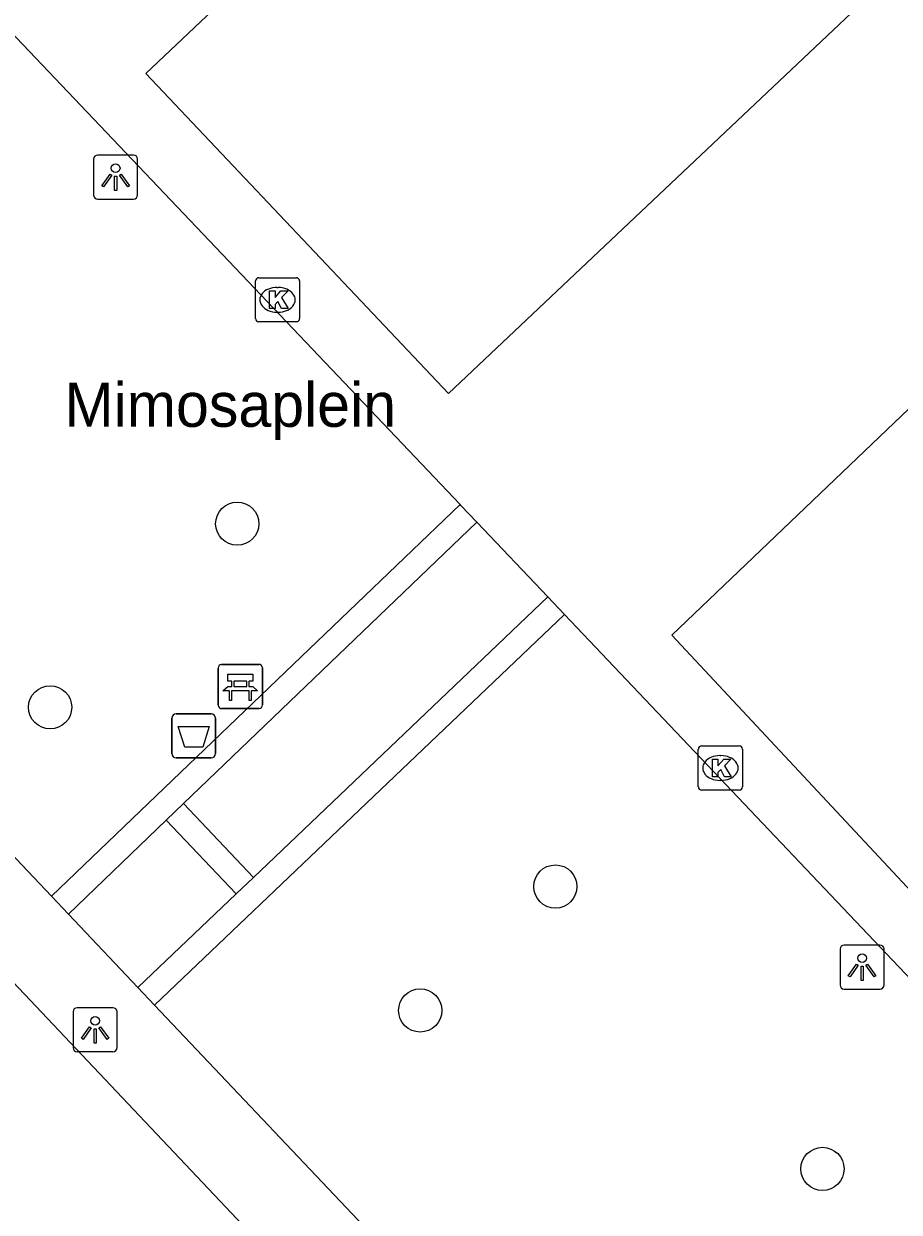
# Model space of a CAD drawing. Extents: x 162347 to 162868, y 381221 to 381813.
# Drawn here: x 162638.63 to 162658.45, y 381348.99 to 381375.9 of the extents above; entities that cross this region are included whole.
import ezdxf

# ---------------------------------------------------------------- set-up
doc = ezdxf.new("R2010")
doc.units = 0
for name, color, linetype in [('IMGEO_Afvalbak', 7, 'Continuous'), ('IMGEO_Bank', 7, 'Continuous'), ('IMGEO_Boom', 7, 'Continuous'), ('IMGEO_Kolk', 7, 'Continuous'), ('IMGEO_Lichtpunt', 7, 'Continuous'), ('IMGEO_Openbare_ruimte_label', 7, 'Continuous'), ('IMGEO_Rijbaan_lokaal_gesloten', 7, 'Continuous'), ('IMGEO_Rijbaan_lokaal_open', 7, 'Continuous'), ('IMGEO_Voetpad_open', 7, 'Continuous')]:
    doc.layers.add(name, color=color, linetype=linetype)

msp = doc.modelspace()

# ---------------------------------------------------------------- linework, layer by layer
at = {"layer": 'IMGEO_Afvalbak'}
for p, q in [((162641.982, 381359.38), (162641.982, 381360.18)), ((162641.982, 381360.18), (162641.982, 381359.38)), ((162642.082, 381360.28), (162642.872, 381360.28)), ((162642.872, 381360.28), (162642.082, 381360.28)), ((162642.972, 381360.18), (162642.972, 381359.38)), ((162642.972, 381359.38), (162642.972, 381360.18)), ((162642.872, 381359.28), (162642.082, 381359.28)), ((162642.082, 381359.28), (162642.872, 381359.28))]:
    msp.add_line(p, q, dxfattribs=at)
msp.add_lwpolyline([(162642.125, 381359.994), (162642.829, 381359.994), (162642.68, 381359.524), (162642.274, 381359.524), (162642.125, 381359.994)], dxfattribs=at)
for centre, start, end in [((162642.082, 381360.18), 90, 180), ((162642.082, 381360.18), 90, 180), ((162642.872, 381360.18), 0, 90), ((162642.872, 381360.18), 360, 90), ((162642.082, 381359.38), 180, 270), ((162642.082, 381359.38), 180, 270), ((162642.872, 381359.38), 270, 0), ((162642.872, 381359.38), 270, 0)]:
    msp.add_arc(centre, 0.1, start, end, dxfattribs=at)
at = {"layer": 'IMGEO_Bank'}
for p, q in [((162643.107, 381361.399), (162643.948, 381361.399)), ((162643.948, 381361.399), (162643.107, 381361.399)), ((162643.032, 381360.474), (162643.032, 381361.315)), ((162643.032, 381361.315), (162643.032, 381360.474)), ((162644.032, 381361.324), (162644.032, 381360.483)), ((162644.032, 381360.483), (162644.032, 381361.324)), ((162643.341, 381360.905), (162643.341, 381361.011)), ((162643.385, 381361.011), (162643.385, 381360.905)), ((162643.673, 381361.017), (162643.391, 381361.017)), ((162643.391, 381360.899), (162643.673, 381360.899)), ((162643.679, 381360.905), (162643.679, 381361.011)), ((162643.723, 381361.011), (162643.723, 381360.905)), ((162643.729, 381360.797), (162643.336, 381360.797)), ((162643.957, 381360.399), (162643.116, 381360.399)), ((162643.116, 381360.399), (162643.957, 381360.399))]:
    msp.add_line(p, q, dxfattribs=at)
for points in [[(162643.335, 381361.017), (162643.249, 381361.017), (162643.249, 381361.178), (162643.812, 381361.178), (162643.812, 381361.017), (162643.729, 381361.017)], [(162643.279, 381360.797), (162643.137, 381360.797), (162643.249, 381360.899), (162643.335, 381360.899)], [(162643.729, 381360.899), (162643.812, 381360.899), (162643.924, 381360.797), (162643.785, 381360.797)], [(162643.329, 381360.79), (162643.329, 381360.583), (162643.286, 381360.583), (162643.286, 381360.79)], [(162643.779, 381360.79), (162643.779, 381360.583), (162643.735, 381360.583), (162643.735, 381360.79)]]:
    msp.add_lwpolyline(points, dxfattribs=at)
for centre, radius, start, end in [((162643.11, 381361.321), 0.0779, 92.4484, 184.2845), ((162643.11, 381361.321), 0.0779, 92.4484, 184.2845), ((162643.954, 381361.321), 0.0779, 2.4484, 94.2845), ((162643.954, 381361.321), 0.0779, 2.4484, 94.2845), ((162643.334, 381361.01), 0.00671, 2.8957, 87.1043), ((162643.334, 381360.906), 0.00671, 272.8957, 357.1043), ((162643.391, 381361.01), 0.00671, 92.8957, 177.1043), ((162643.391, 381360.906), 0.00671, 182.8957, 267.1043), ((162643.673, 381361.01), 0.00671, 2.8957, 87.1043), ((162643.673, 381360.906), 0.00671, 272.8957, 357.1043), ((162643.73, 381361.01), 0.00671, 92.8957, 177.1043), ((162643.73, 381360.906), 0.00671, 182.8957, 267.1043), ((162643.279, 381360.79), 0.00671, 2.8957, 87.1043), ((162643.336, 381360.79), 0.00671, 92.8957, 177.1043), ((162643.728, 381360.79), 0.00671, 2.8957, 87.1043), ((162643.785, 381360.79), 0.00671, 92.8957, 177.1043), ((162643.11, 381360.477), 0.0779, 182.4484, 274.2845), ((162643.11, 381360.477), 0.0779, 182.4484, 274.2845), ((162643.954, 381360.477), 0.0779, 272.4484, 4.2845), ((162643.954, 381360.477), 0.0779, 272.4484, 4.2845)]:
    msp.add_arc(centre, radius, start, end, dxfattribs=at)
at = {"layer": 'IMGEO_Boom'}
for centre in [(162643.463, 381364.584), (162639.227, 381360.428), (162650.665, 381356.369), (162647.605, 381353.563), (162656.712, 381349.975)]:
    msp.add_circle(centre, 0.489, dxfattribs=at)
at = {"layer": 'IMGEO_Kolk'}
for p, q in [((162643.874, 381369.228), (162643.874, 381370.08)), ((162643.949, 381370.154), (162644.801, 381370.154)), ((162644.875, 381370.08), (162644.875, 381369.228)), ((162644.362, 381369.934), (162644.387, 381369.934)), ((162644.385, 381369.374), (162644.36, 381369.374)), ((162644.801, 381369.154), (162643.949, 381369.154)), ((162653.976, 381359.553), (162654.828, 381359.553)), ((162653.901, 381358.627), (162653.901, 381359.479)), ((162654.389, 381359.333), (162654.414, 381359.333)), ((162654.902, 381359.479), (162654.902, 381358.627)), ((162654.412, 381358.773), (162654.387, 381358.773)), ((162654.828, 381358.553), (162653.976, 381358.553))]:
    msp.add_line(p, q, dxfattribs=at)
for points in [[(162643.874, 381369.228), (162643.874, 381370.08)], [(162643.949, 381370.154), (162644.801, 381370.154)], [(162644.875, 381370.08), (162644.875, 381369.228)], [(162644.195, 381369.854), (162644.318, 381369.854), (162644.318, 381369.703), (162644.448, 381369.854), (162644.612, 381369.854), (162644.466, 381369.703), (162644.619, 381369.454), (162644.467, 381369.454), (162644.382, 381369.618), (162644.318, 381369.551), (162644.318, 381369.454), (162644.195, 381369.454), (162644.195, 381369.854)], [(162644.801, 381369.154), (162643.949, 381369.154)], [(162653.976, 381359.553), (162654.828, 381359.553)], [(162653.901, 381358.627), (162653.901, 381359.479)], [(162654.222, 381359.253), (162654.345, 381359.253), (162654.345, 381359.102), (162654.475, 381359.253), (162654.639, 381359.253), (162654.493, 381359.102), (162654.646, 381358.853), (162654.494, 381358.853), (162654.409, 381359.017), (162654.345, 381358.95), (162654.345, 381358.853), (162654.222, 381358.853), (162654.222, 381359.253)], [(162654.902, 381359.479), (162654.902, 381358.627)], [(162654.828, 381358.553), (162653.976, 381358.553)]]:
    msp.add_lwpolyline(points, dxfattribs=at)
for centre, start, end in [((162643.951, 381370.078), 91.552, 178.448), ((162643.951, 381370.078), 91.552, 178.448), ((162644.799, 381370.078), 1.552, 88.448), ((162644.799, 381370.078), 1.552, 88.448), ((162643.951, 381369.23), 181.552, 268.448), ((162643.951, 381369.23), 181.552, 268.448), ((162644.799, 381369.23), 271.552, 358.448), ((162644.799, 381369.23), 271.552, 358.448), ((162653.978, 381359.477), 91.552, 178.448), ((162653.978, 381359.477), 91.552, 178.448), ((162654.826, 381359.477), 1.552, 88.448), ((162654.826, 381359.477), 1.552, 88.448), ((162653.978, 381358.629), 181.552, 268.448), ((162653.978, 381358.629), 181.552, 268.448), ((162654.826, 381358.629), 271.552, 358.448), ((162654.826, 381358.629), 271.552, 358.448)]:
    msp.add_arc(centre, 0.0765, start, end, dxfattribs=at)
for centre, major_axis, ratio, start_param, end_param in [((162644.361, 381369.654), (-0.387, 0.002), 0.722429, 4.712389, 7.853982), ((162644.386, 381369.654), (-0.39, 0.002), 0.717154, 1.570796, 4.712389), ((162654.388, 381359.053), (-0.387, 0.002), 0.722429, 4.712389, 7.853982), ((162654.413, 381359.053), (-0.39, 0.002), 0.717154, 1.570796, 4.712389)]:
    msp.add_ellipse(centre, major_axis=major_axis, ratio=ratio, start_param=start_param, end_param=end_param, dxfattribs=at)
at = {"layer": 'IMGEO_Lichtpunt'}
for p, q in [((162640.21, 381372.837), (162640.21, 381372.03)), ((162640.21, 381372.837), (162640.21, 381372.03)), ((162641.112, 381372.932), (162640.304, 381372.932)), ((162641.112, 381372.932), (162640.304, 381372.932)), ((162641.206, 381372.03), (162641.206, 381372.837)), ((162641.206, 381372.03), (162641.206, 381372.837)), ((162640.304, 381371.936), (162641.112, 381371.936)), ((162640.304, 381371.936), (162641.112, 381371.936)), ((162657.11, 381354.949), (162657.11, 381354.142)), ((162657.11, 381354.949), (162657.11, 381354.142)), ((162658.012, 381355.044), (162657.204, 381355.044)), ((162658.012, 381355.044), (162657.204, 381355.044)), ((162658.106, 381354.142), (162658.106, 381354.949)), ((162658.106, 381354.142), (162658.106, 381354.949)), ((162657.204, 381354.048), (162658.012, 381354.048)), ((162657.204, 381354.048), (162658.012, 381354.048)), ((162640.648, 381353.626), (162639.84, 381353.626)), ((162640.648, 381353.626), (162639.84, 381353.626)), ((162639.746, 381353.531), (162639.746, 381352.724)), ((162639.746, 381353.531), (162639.746, 381352.724)), ((162640.742, 381352.724), (162640.742, 381353.531)), ((162640.742, 381352.724), (162640.742, 381353.531)), ((162639.84, 381352.63), (162640.648, 381352.63)), ((162639.84, 381352.63), (162640.648, 381352.63))]:
    msp.add_line(p, q, dxfattribs=at)
for points in [[(162640.584, 381372.501), (162640.623, 381372.473), (162640.435, 381372.211), (162640.397, 381372.238), (162640.584, 381372.501)], [(162640.686, 381372.453), (162640.733, 381372.453), (162640.733, 381372.131), (162640.686, 381372.131), (162640.686, 381372.453)], [(162640.796, 381372.473), (162640.834, 381372.5), (162641.021, 381372.238), (162640.982, 381372.21), (162640.796, 381372.473)], [(162657.484, 381354.613), (162657.523, 381354.585), (162657.335, 381354.323), (162657.297, 381354.35), (162657.484, 381354.613)], [(162657.586, 381354.565), (162657.633, 381354.565), (162657.633, 381354.243), (162657.586, 381354.243), (162657.586, 381354.565)], [(162657.696, 381354.585), (162657.734, 381354.612), (162657.921, 381354.35), (162657.882, 381354.322), (162657.696, 381354.585)], [(162640.12, 381353.195), (162640.159, 381353.167), (162639.971, 381352.905), (162639.933, 381352.932), (162640.12, 381353.195)], [(162640.222, 381353.147), (162640.269, 381353.147), (162640.269, 381352.825), (162640.222, 381352.825), (162640.222, 381353.147)], [(162640.332, 381353.167), (162640.37, 381353.194), (162640.557, 381352.932), (162640.518, 381352.904), (162640.332, 381353.167)]]:
    msp.add_lwpolyline(points, dxfattribs=at)
for centre in [(162640.709, 381372.635), (162657.609, 381354.747), (162640.245, 381353.329)]:
    msp.add_circle(centre, 0.0994, dxfattribs=at)
for centre, start, end in [((162640.304, 381372.837), 90, 180), ((162640.304, 381372.837), 90, 180), ((162641.112, 381372.837), 0, 90), ((162641.112, 381372.837), 0, 90), ((162640.304, 381372.03), 180, 270), ((162640.304, 381372.03), 180, 270), ((162641.112, 381372.03), 270, 0), ((162641.112, 381372.03), 270, 360), ((162657.204, 381354.949), 90, 180), ((162657.204, 381354.949), 90, 180), ((162658.012, 381354.949), 0, 90), ((162658.012, 381354.949), 0, 90), ((162657.204, 381354.142), 180, 270), ((162657.204, 381354.142), 180, 270), ((162658.012, 381354.142), 270, 0), ((162658.012, 381354.142), 270, 360), ((162639.84, 381353.531), 90, 180), ((162639.84, 381353.531), 90, 180), ((162640.648, 381353.531), 0, 90), ((162640.648, 381353.531), 0, 90), ((162639.84, 381352.724), 180, 270), ((162639.84, 381352.724), 180, 270), ((162640.648, 381352.724), 270, 0), ((162640.648, 381352.724), 270, 360)]:
    msp.add_arc(centre, 0.0946, start, end, dxfattribs=at)
at = {"layer": 'IMGEO_Rijbaan_lokaal_gesloten'}
msp.add_lwpolyline([(162656.018, 381335.583), (162653.74, 381337.977), (162644.499, 381347.735), (162631.221, 381361.785), (162624.744, 381368.671), (162624.577, 381368.822)], dxfattribs=at)
at = {"layer": 'IMGEO_Rijbaan_lokaal_open'}
for points in [[(162648.242, 381367.534), (162660.494, 381379.112), (162653.635, 381386.354), (162641.396, 381374.775), (162648.242, 381367.534)], [(162636.127, 381378.045), (162648.509, 381365.016)], [(162672.396, 381366.482), (162665.548, 381373.756), (162653.3, 381362.059), (162660.118, 381354.759), (162672.396, 381366.482)], [(162648.885, 381364.621), (162648.526, 381364.999), (162648.509, 381365.016)], [(162650.496, 381362.927), (162648.885, 381364.621)], [(162650.875, 381362.529), (162650.496, 381362.927)], [(162650.875, 381362.529), (162663.207, 381349.526)]]:
    msp.add_lwpolyline(points, dxfattribs=at)
at = {"layer": 'IMGEO_Voetpad_open'}
for points in [[(162639.256, 381356.15), (162625.878, 381370.278)], [(162648.509, 381365.016), (162644.73, 381361.395), (162639.256, 381356.15)], [(162642.247, 381358.249), (162648.885, 381364.621)], [(162650.496, 381362.927), (162643.829, 381356.574)], [(162641.591, 381353.684), (162650.875, 381362.529)], [(162641.853, 381357.871), (162642.247, 381358.249)], [(162642.247, 381358.249), (162643.829, 381356.574)], [(162639.639, 381355.746), (162641.853, 381357.871)], [(162643.437, 381356.2), (162641.853, 381357.871)], [(162643.829, 381356.574), (162643.437, 381356.2)], [(162639.256, 381356.15), (162639.639, 381355.746)], [(162643.437, 381356.2), (162641.214, 381354.082)], [(162639.639, 381355.746), (162641.214, 381354.082)], [(162641.214, 381354.082), (162641.591, 381353.684)], [(162641.591, 381353.684), (162657.461, 381336.924)]]:
    msp.add_lwpolyline(points, dxfattribs=at)

# ---------------------------------------------------------------- texts
at = {"layer": 'IMGEO_Openbare_ruimte_label'}
msp.add_text('Mimosaplein', height=1, dxfattribs=at).set_placement((162639.551, 381366.778))

doc.saveas('drawing.dxf')
